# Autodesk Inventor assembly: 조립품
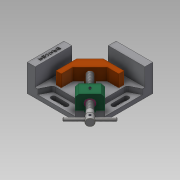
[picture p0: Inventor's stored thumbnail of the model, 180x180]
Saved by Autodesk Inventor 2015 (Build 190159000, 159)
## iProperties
Created: 2019-04
Part Number: 조립품
Document SubType Name: Assembly
Designer: SCD-A02
Author: SCD-A02
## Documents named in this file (11)
- C:\Users\SCD-A02\Desktop\490408V1008\조립품.iam
- C:\Users\SCD-A02\Desktop\490408V1008\베이스.ipt
- C:\Users\SCD-A02\Desktop\490408V1008\리드스크류.ipt
- C:\Users\SCD-A02\Desktop\490408V1008\핸들.ipt
- C:\Users\SCD-A02\Desktop\490408V1008\멈춤나사 M4x5.ipt
- C:\Users\SCD-A02\Desktop\490408V1008\서포트.ipt
- C:\Users\SCD-A02\Desktop\490408V1008\멈춤나사 M4x10.ipt
- C:\Users\SCD-A02\Desktop\490408V1008\볼트 M4x16.ipt
- C:\Users\SCD-A02\Desktop\490408V1008\조.ipt
- C:\Users\SCD-A02\Desktop\490408V1008\평행 핀 2.5x24.ipt
- C:\Users\SCD-A02\Desktop\490408V1008\부시.ipt
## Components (1 placed, 1 different names)
1. 핸들:1
